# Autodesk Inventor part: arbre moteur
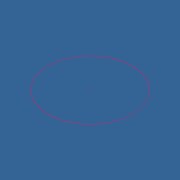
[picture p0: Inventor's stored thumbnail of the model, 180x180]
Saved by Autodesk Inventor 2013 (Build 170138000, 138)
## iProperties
Created: 2011-10
Part Number: arbre moteur
Material: Acier allié
Document SubType Name: Modeling
Designer: Laur
Mass: 0.147044 g
Surface Area: 0.534856 cm^2
Volume: 0.0187317 cm^3
Density: 7.85 g/cm^3
Author: Laur
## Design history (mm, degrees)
sketch "Esquisse1"
  geometry: C1 r 0.75 at (0, 0) reference
  dimensions: "d0" = 10.6 dimension on C1.centre C1
extrude "Extrusion1" new body sketch "Esquisse1" stored distance "d0" = 10.6; taper "d1" = 0 deg
node "Solide1"
node "Corps solides"
node "Corps surfaciques"
node "Référence1"
